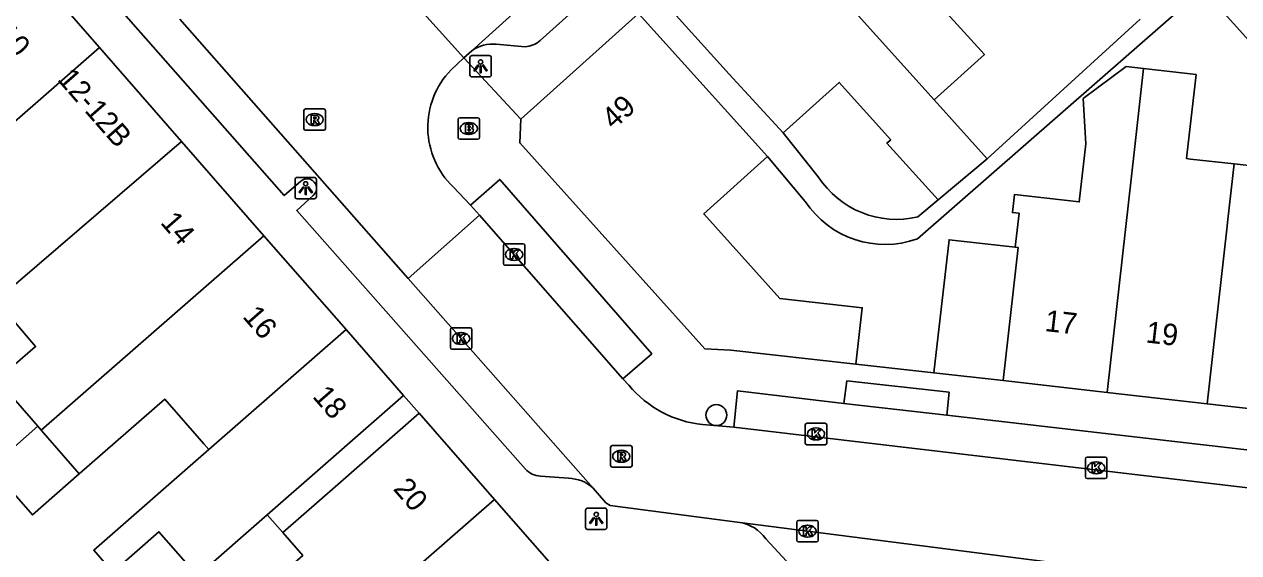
# Model space of a CAD drawing. Extents: x 162172 to 163187, y 382874 to 383684.
# Drawn here: x 162658.8 to 162715.5, y 383404.9 to 383429.6 of the extents above; entities that cross this region are included whole.
import ezdxf

# ---------------------------------------------------------------- set-up
doc = ezdxf.new("R2010")
doc.units = 0
for name, color, linetype in [('IMGEO_Boom', 7, 'Continuous'), ('IMGEO_Brandkraan', 7, 'Continuous'), ('IMGEO_Kolk', 7, 'Continuous'), ('IMGEO_Lichtpunt', 7, 'Continuous'), ('IMGEO_Pand', 7, 'Continuous'), ('IMGEO_Pand_nummerreeks', 7, 'Continuous'), ('IMGEO_Pand_overbouw', 7, 'Continuous'), ('IMGEO_Rijbaan_lokaal_open', 7, 'Continuous'), ('IMGEO_Rioolput', 7, 'Continuous'), ('IMGEO_Voetpad_open', 7, 'Continuous')]:
    doc.layers.add(name, color=color, linetype=linetype)

msp = doc.modelspace()

# ---------------------------------------------------------------- linework, layer by layer
at = {"layer": 'IMGEO_Boom'}
msp.add_circle((162691.134, 383411.373), 0.489, dxfattribs=at)
at = {"layer": 'IMGEO_Brandkraan'}
for p, q in [((162679.07, 383424.336), (162679.07, 383425.188)), ((162679.145, 383425.262), (162679.997, 383425.262)), ((162680.071, 383425.188), (162680.071, 383424.336)), ((162679.558, 383425.042), (162679.583, 383425.042)), ((162679.997, 383424.262), (162679.145, 383424.262)), ((162679.581, 383424.482), (162679.556, 383424.482))]:
    msp.add_line(p, q, dxfattribs=at)
for points in [[(162679.07, 383424.336), (162679.07, 383425.188)], [(162679.145, 383425.262), (162679.997, 383425.262)], [(162680.071, 383425.188), (162680.071, 383424.336)], [(162679.418, 383424.962), (162679.418, 383424.562), (162679.631, 383424.562)], [(162679.649, 383424.962), (162679.418, 383424.962)], [(162679.597, 383424.881), (162679.543, 383424.881), (162679.543, 383424.805)], [(162679.543, 383424.805), (162679.596, 383424.805)], [(162679.605, 383424.729), (162679.543, 383424.729), (162679.543, 383424.648)], [(162679.543, 383424.648), (162679.605, 383424.648)], [(162679.997, 383424.262), (162679.145, 383424.262)]]:
    msp.add_lwpolyline(points, dxfattribs=at)
for centre, radius, start, end in [((162679.147, 383425.186), 0.0765, 91.552, 178.448), ((162679.147, 383425.186), 0.0765, 91.552, 178.448), ((162679.995, 383425.186), 0.0765, 1.552, 88.448), ((162679.995, 383425.186), 0.0765, 1.552, 88.448), ((162679.598, 383424.843), 0.0379, 267.8285, 90.9355), ((162679.606, 383424.688), 0.0404, 269.8759, 90.5077), ((162679.637, 383424.813), 0.251, 268.6676, 293.5347), ((162679.653, 383424.817), 0.145, 59.4692, 91.5367), ((162679.678, 383424.864), 0.0922, 285.5137, 58.1501), ((162679.683, 383424.672), 0.105, 301.3115, 78.989), ((162679.147, 383424.338), 0.0765, 181.552, 268.448), ((162679.147, 383424.338), 0.0765, 181.552, 268.448), ((162679.995, 383424.338), 0.0765, 271.552, 358.448), ((162679.995, 383424.338), 0.0765, 271.552, 358.448)]:
    msp.add_arc(centre, radius, start, end, dxfattribs=at)
for centre, major_axis, ratio, start_param, end_param in [((162679.557, 383424.762), (-0.387, 0.002), 0.722429, 4.712389, 7.853982), ((162679.582, 383424.762), (-0.39, 0.002), 0.717154, 1.570796, 4.712389)]:
    msp.add_ellipse(centre, major_axis=major_axis, ratio=ratio, start_param=start_param, end_param=end_param, dxfattribs=at)
at = {"layer": 'IMGEO_Kolk'}
for p, q in [((162681.186, 383418.45), (162681.186, 383419.302)), ((162681.261, 383419.376), (162682.113, 383419.376)), ((162681.674, 383419.156), (162681.699, 383419.156)), ((162682.187, 383419.302), (162682.187, 383418.45)), ((162682.113, 383418.376), (162681.261, 383418.376)), ((162681.697, 383418.596), (162681.672, 383418.596)), ((162678.71, 383414.524), (162678.71, 383415.376)), ((162678.785, 383415.45), (162679.637, 383415.45)), ((162679.198, 383415.23), (162679.223, 383415.23)), ((162679.711, 383415.376), (162679.711, 383414.524)), ((162679.637, 383414.45), (162678.785, 383414.45)), ((162679.221, 383414.67), (162679.196, 383414.67)), ((162695.364, 383410.991), (162696.216, 383410.991)), ((162695.289, 383410.065), (162695.289, 383410.917)), ((162695.777, 383410.771), (162695.802, 383410.771)), ((162696.29, 383410.917), (162696.29, 383410.065)), ((162696.216, 383409.991), (162695.364, 383409.991)), ((162695.8, 383410.211), (162695.775, 383410.211)), ((162708.373, 383408.484), (162708.373, 383409.336)), ((162708.448, 383409.41), (162709.3, 383409.41)), ((162709.374, 383409.336), (162709.374, 383408.484)), ((162708.861, 383409.19), (162708.886, 383409.19)), ((162709.3, 383408.41), (162708.448, 383408.41)), ((162708.884, 383408.63), (162708.859, 383408.63)), ((162694.965, 383406.452), (162695.817, 383406.452)), ((162694.89, 383405.526), (162694.89, 383406.378)), ((162695.378, 383406.232), (162695.403, 383406.232)), ((162695.891, 383406.378), (162695.891, 383405.526)), ((162695.817, 383405.452), (162694.965, 383405.452)), ((162695.401, 383405.672), (162695.376, 383405.672))]:
    msp.add_line(p, q, dxfattribs=at)
for points in [[(162681.186, 383418.45), (162681.186, 383419.302)], [(162681.261, 383419.376), (162682.113, 383419.376)], [(162681.507, 383419.076), (162681.63, 383419.076), (162681.63, 383418.925), (162681.76, 383419.076), (162681.924, 383419.076), (162681.778, 383418.925), (162681.931, 383418.676), (162681.779, 383418.676), (162681.694, 383418.84), (162681.63, 383418.773), (162681.63, 383418.676), (162681.507, 383418.676), (162681.507, 383419.076)], [(162682.187, 383419.302), (162682.187, 383418.45)], [(162682.113, 383418.376), (162681.261, 383418.376)], [(162678.71, 383414.524), (162678.71, 383415.376)], [(162678.785, 383415.45), (162679.637, 383415.45)], [(162679.031, 383415.15), (162679.154, 383415.15), (162679.154, 383414.999), (162679.284, 383415.15), (162679.448, 383415.15), (162679.302, 383414.999), (162679.455, 383414.75), (162679.303, 383414.75), (162679.218, 383414.914), (162679.154, 383414.847), (162679.154, 383414.75), (162679.031, 383414.75), (162679.031, 383415.15)], [(162679.711, 383415.376), (162679.711, 383414.524)], [(162679.637, 383414.45), (162678.785, 383414.45)], [(162695.364, 383410.991), (162696.216, 383410.991)], [(162695.289, 383410.065), (162695.289, 383410.917)], [(162695.61, 383410.691), (162695.733, 383410.691), (162695.733, 383410.54), (162695.863, 383410.691), (162696.027, 383410.691), (162695.881, 383410.54), (162696.034, 383410.291), (162695.882, 383410.291), (162695.797, 383410.455), (162695.733, 383410.388), (162695.733, 383410.291), (162695.61, 383410.291), (162695.61, 383410.691)], [(162696.29, 383410.917), (162696.29, 383410.065)], [(162696.216, 383409.991), (162695.364, 383409.991)], [(162708.373, 383408.484), (162708.373, 383409.336)], [(162708.448, 383409.41), (162709.3, 383409.41)], [(162709.374, 383409.336), (162709.374, 383408.484)], [(162708.694, 383409.11), (162708.817, 383409.11), (162708.817, 383408.959), (162708.947, 383409.11), (162709.111, 383409.11), (162708.965, 383408.959), (162709.118, 383408.71), (162708.966, 383408.71), (162708.881, 383408.874), (162708.817, 383408.807), (162708.817, 383408.71), (162708.694, 383408.71), (162708.694, 383409.11)], [(162709.3, 383408.41), (162708.448, 383408.41)], [(162694.965, 383406.452), (162695.817, 383406.452)], [(162694.89, 383405.526), (162694.89, 383406.378)], [(162695.211, 383406.152), (162695.334, 383406.152), (162695.334, 383406.001), (162695.464, 383406.152), (162695.628, 383406.152), (162695.482, 383406.001), (162695.635, 383405.752), (162695.483, 383405.752), (162695.398, 383405.916), (162695.334, 383405.849), (162695.334, 383405.752), (162695.211, 383405.752), (162695.211, 383406.152)], [(162695.891, 383406.378), (162695.891, 383405.526)], [(162695.817, 383405.452), (162694.965, 383405.452)]]:
    msp.add_lwpolyline(points, dxfattribs=at)
for centre, start, end in [((162681.263, 383419.3), 91.552, 178.448), ((162681.263, 383419.3), 91.552, 178.448), ((162682.111, 383419.3), 1.552, 88.448), ((162682.111, 383419.3), 1.552, 88.448), ((162681.263, 383418.452), 181.552, 268.448), ((162681.263, 383418.452), 181.552, 268.448), ((162682.111, 383418.452), 271.552, 358.448), ((162682.111, 383418.452), 271.552, 358.448), ((162678.787, 383415.374), 91.552, 178.448), ((162678.787, 383415.374), 91.552, 178.448), ((162679.635, 383415.374), 1.552, 88.448), ((162679.635, 383415.374), 1.552, 88.448), ((162678.787, 383414.526), 181.552, 268.448), ((162678.787, 383414.526), 181.552, 268.448), ((162679.635, 383414.526), 271.552, 358.448), ((162679.635, 383414.526), 271.552, 358.448), ((162695.366, 383410.915), 91.552, 178.448), ((162695.366, 383410.915), 91.552, 178.448), ((162696.214, 383410.915), 1.552, 88.448), ((162696.214, 383410.915), 1.552, 88.448), ((162695.366, 383410.067), 181.552, 268.448), ((162695.366, 383410.067), 181.552, 268.448), ((162696.214, 383410.067), 271.552, 358.448), ((162696.214, 383410.067), 271.552, 358.448), ((162708.45, 383409.334), 91.552, 178.448), ((162708.45, 383409.334), 91.552, 178.448), ((162709.298, 383409.334), 1.552, 88.448), ((162709.298, 383409.334), 1.552, 88.448), ((162708.45, 383408.486), 181.552, 268.448), ((162708.45, 383408.486), 181.552, 268.448), ((162709.298, 383408.486), 271.552, 358.448), ((162709.298, 383408.486), 271.552, 358.448), ((162694.967, 383406.376), 91.552, 178.448), ((162694.967, 383406.376), 91.552, 178.448), ((162695.815, 383406.376), 1.552, 88.448), ((162695.815, 383406.376), 1.552, 88.448), ((162694.967, 383405.528), 181.552, 268.448), ((162694.967, 383405.528), 181.552, 268.448), ((162695.815, 383405.528), 271.552, 358.448), ((162695.815, 383405.528), 271.552, 358.448)]:
    msp.add_arc(centre, 0.0765, start, end, dxfattribs=at)
for centre, major_axis, ratio, start_param, end_param in [((162681.673, 383418.876), (-0.387, 0.002), 0.722429, 4.712389, 7.853982), ((162681.698, 383418.876), (-0.39, 0.002), 0.717154, 1.570796, 4.712389), ((162679.197, 383414.95), (-0.387, 0.002), 0.722429, 4.712389, 7.853982), ((162679.222, 383414.95), (-0.39, 0.002), 0.717154, 1.570796, 4.712389), ((162695.776, 383410.491), (-0.387, 0.002), 0.722429, 4.712389, 7.853982), ((162695.801, 383410.491), (-0.39, 0.002), 0.717154, 1.570796, 4.712389), ((162708.86, 383408.91), (-0.387, 0.002), 0.722429, 4.712389, 7.853982), ((162708.885, 383408.91), (-0.39, 0.002), 0.717154, 1.570796, 4.712389), ((162695.377, 383405.952), (-0.387, 0.002), 0.722429, 4.712389, 7.853982), ((162695.402, 383405.952), (-0.39, 0.002), 0.717154, 1.570796, 4.712389)]:
    msp.add_ellipse(centre, major_axis=major_axis, ratio=ratio, start_param=start_param, end_param=end_param, dxfattribs=at)
at = {"layer": 'IMGEO_Lichtpunt'}
for p, q in [((162679.624, 383428.071), (162679.624, 383427.264)), ((162679.624, 383428.071), (162679.624, 383427.264)), ((162680.526, 383428.166), (162679.718, 383428.166)), ((162680.526, 383428.166), (162679.718, 383428.166)), ((162680.62, 383427.264), (162680.62, 383428.071)), ((162680.62, 383427.264), (162680.62, 383428.071)), ((162679.718, 383427.17), (162680.526, 383427.17)), ((162679.718, 383427.17), (162680.526, 383427.17)), ((162671.454, 383422.378), (162671.454, 383421.571)), ((162671.454, 383422.378), (162671.454, 383421.571)), ((162672.356, 383422.473), (162671.548, 383422.473)), ((162672.356, 383422.473), (162671.548, 383422.473)), ((162672.45, 383421.571), (162672.45, 383422.378)), ((162672.45, 383421.571), (162672.45, 383422.378)), ((162671.548, 383421.477), (162672.356, 383421.477)), ((162671.548, 383421.477), (162672.356, 383421.477)), ((162685.928, 383407.028), (162685.12, 383407.028)), ((162685.928, 383407.028), (162685.12, 383407.028)), ((162685.026, 383406.933), (162685.026, 383406.126)), ((162685.026, 383406.933), (162685.026, 383406.126)), ((162686.022, 383406.126), (162686.022, 383406.933)), ((162686.022, 383406.126), (162686.022, 383406.933)), ((162685.12, 383406.032), (162685.928, 383406.032)), ((162685.12, 383406.032), (162685.928, 383406.032))]:
    msp.add_line(p, q, dxfattribs=at)
for points in [[(162679.998, 383427.735), (162680.037, 383427.707), (162679.849, 383427.445), (162679.811, 383427.472), (162679.998, 383427.735)], [(162680.1, 383427.687), (162680.147, 383427.687), (162680.147, 383427.365), (162680.1, 383427.365), (162680.1, 383427.687)], [(162680.21, 383427.707), (162680.248, 383427.734), (162680.435, 383427.472), (162680.396, 383427.444), (162680.21, 383427.707)], [(162671.828, 383422.042), (162671.867, 383422.014), (162671.679, 383421.752), (162671.641, 383421.779), (162671.828, 383422.042)], [(162671.93, 383421.994), (162671.977, 383421.994), (162671.977, 383421.672), (162671.93, 383421.672), (162671.93, 383421.994)], [(162672.04, 383422.014), (162672.078, 383422.041), (162672.265, 383421.779), (162672.226, 383421.751), (162672.04, 383422.014)], [(162685.4, 383406.597), (162685.439, 383406.569), (162685.251, 383406.307), (162685.213, 383406.334), (162685.4, 383406.597)], [(162685.502, 383406.549), (162685.549, 383406.549), (162685.549, 383406.227), (162685.502, 383406.227), (162685.502, 383406.549)], [(162685.612, 383406.569), (162685.65, 383406.596), (162685.837, 383406.334), (162685.798, 383406.306), (162685.612, 383406.569)]]:
    msp.add_lwpolyline(points, dxfattribs=at)
for centre in [(162680.123, 383427.869), (162671.953, 383422.176), (162685.525, 383406.731)]:
    msp.add_circle(centre, 0.0994, dxfattribs=at)
for centre, start, end in [((162679.718, 383428.071), 90, 180), ((162679.718, 383428.071), 90, 180), ((162680.526, 383428.071), 0, 90), ((162680.526, 383428.071), 0, 90), ((162679.718, 383427.264), 180, 270), ((162679.718, 383427.264), 180, 270), ((162680.526, 383427.264), 270, 0), ((162680.526, 383427.264), 270, 360), ((162671.548, 383422.378), 90, 180), ((162671.548, 383422.378), 90, 180), ((162672.356, 383422.378), 0, 90), ((162672.356, 383422.378), 0, 90), ((162671.548, 383421.571), 180, 270), ((162671.548, 383421.571), 180, 270), ((162672.356, 383421.571), 270, 0), ((162672.356, 383421.571), 270, 360), ((162685.12, 383406.933), 90, 180), ((162685.12, 383406.933), 90, 180), ((162685.928, 383406.933), 0, 90), ((162685.928, 383406.933), 0, 90), ((162685.12, 383406.126), 180, 270), ((162685.12, 383406.126), 180, 270), ((162685.928, 383406.126), 270, 0), ((162685.928, 383406.126), 270, 360)]:
    msp.add_arc(centre, 0.0946, start, end, dxfattribs=at)
at = {"layer": 'IMGEO_Pand'}
for points in [[(162701.304, 383426.1), (162693.085, 383435.246)], [(162701.304, 383426.1), (162703.652, 383428.211), (162701.261, 383430.871), (162703.723, 383433.084)], [(162658.471, 383432.944), (162662.315, 383428.547)], [(162694.249, 383424.557), (162691.729, 383427.304), (162688.386, 383431.022)], [(162687.503, 383430.138), (162682.005, 383425.195)], [(162687.503, 383430.138), (162693.52, 383423.445)], [(162662.315, 383428.547), (162655.851, 383422.895)], [(162666.159, 383424.151), (162662.315, 383428.547)], [(162705.098, 383419.217), (162705.277, 383420.801), (162704.964, 383420.836), (162705.058, 383421.671), (162708.086, 383421.328), (162708.393, 383424.04), (162708.273, 383426.159), (162710.274, 383427.651), (162711.093, 383427.559)], [(162709.382, 383412.436), (162710.666, 383423.783), (162711.093, 383427.559)], [(162711.093, 383427.559), (162713.543, 383427.282), (162713.117, 383423.505), (162713.1, 383423.356), (162713.279, 383423.335), (162715.325, 383423.104)], [(162694.249, 383424.557), (162696.875, 383426.916), (162699.282, 383424.238), (162699.103, 383424.077), (162701.49, 383421.421)], [(162703.785, 383423.338), (162701.304, 383426.1)], [(162697.654, 383413.757), (162691.813, 383414.407), (162690.592, 383414.472), (162681.947, 383424.088), (162682.005, 383425.195)], [(162715.325, 383423.104), (162717.531, 383422.854), (162717.804, 383425.263), (162717.817, 383425.378), (162720.286, 383425.098), (162720.273, 383424.984)], [(162657.489, 383416.733), (162666.159, 383424.151)], [(162666.159, 383424.151), (162670.003, 383419.754)], [(162693.52, 383423.445), (162690.546, 383420.771), (162694.105, 383416.814), (162697.946, 383416.386), (162697.654, 383413.757)], [(162703.785, 383423.338), (162701.49, 383421.421)], [(162715.325, 383423.104), (162715.031, 383420.508), (162714.981, 383420.063), (162714.057, 383411.906)], [(162659.603, 383410.662), (162670.003, 383419.754)], [(162670.003, 383419.754), (162673.839, 383415.368)], [(162701.297, 383413.351), (162702.002, 383419.567), (162705.098, 383419.217)], [(162705.098, 383419.217), (162705.236, 383419.2), (162704.532, 383412.985)], [(162657.489, 383416.733), (162659.334, 383414.576), (162657.524, 383413.027), (162657.649, 383412.894), (162659.439, 383410.849)], [(162673.839, 383415.368), (162667.431, 383409.765)], [(162673.839, 383415.368), (162676.527, 383412.293)], [(162704.532, 383412.985), (162701.297, 383413.351)], [(162709.382, 383412.436), (162704.532, 383412.985)], [(162661.379, 383408.632), (162665.368, 383412.123), (162667.196, 383410.034), (162667.431, 383409.765)], [(162667.431, 383409.765), (162662.05, 383405.061), (162662.943, 383404.041), (162665.093, 383405.923), (162666.894, 383403.864), (162670.157, 383406.719), (162672.756, 383408.993), (162676.527, 383412.293)], [(162714.057, 383411.906), (162709.382, 383412.436)], [(162718.732, 383411.377), (162714.057, 383411.906)], [(162677.251, 383411.459), (162673.45, 383408.133), (162670.884, 383405.888), (162671.817, 383404.822), (162667.629, 383401.158), (162670.103, 383398.331), (162670.213, 383398.206)], [(162677.251, 383411.459), (162680.771, 383407.436)], [(162659.439, 383410.849), (162657.247, 383408.93), (162659.187, 383406.714), (162661.379, 383408.632)], [(162659.603, 383410.662), (162659.439, 383410.849)], [(162661.379, 383408.632), (162659.603, 383410.662)], [(162670.213, 383398.206), (162680.771, 383407.436)], [(162680.771, 383407.436), (162684.317, 383403.384), (162687.08, 383403.199)]]:
    msp.add_lwpolyline(points, dxfattribs=at)
at = {"layer": 'IMGEO_Pand_overbouw'}
msp.add_lwpolyline([(162677.251, 383411.459), (162676.527, 383412.293), (162672.756, 383408.993), (162670.157, 383406.719), (162670.884, 383405.888), (162673.45, 383408.133)], close=True, dxfattribs=at)
at = {"layer": 'IMGEO_Rijbaan_lokaal_open'}
for points in [[(162715.496, 383460.436), (162713.601, 383458.84), (162697.961, 383444.869), (162679.717, 383428.393)], [(162679.332, 383428.059), (162676.183, 383431.58)], [(162676.74, 383417.761), (162666.079, 383429.865)], [(162679.332, 383428.059), (162678.73, 383427.487)], [(162679.332, 383428.059), (162679.717, 383428.393)], [(162678.841, 383422.038), (162679.645, 383421.175)], [(162680.069, 383420.719), (162679.645, 383421.175)], [(162680.069, 383420.719), (162676.74, 383417.761)], [(162686.77, 383413.066), (162680.069, 383420.719)], [(162676.74, 383417.761), (162685.378, 383407.959)], [(162687.048, 383412.766), (162686.77, 383413.066)], [(162691.943, 383410.803), (162690.489, 383410.931)], [(162727.575, 383406.608), (162691.943, 383410.803)], [(162692.226, 383406.357), (162692.108, 383406.372), (162686.175, 383407.146), (162685.977, 383407.278), (162685.378, 383407.959)], [(162692.226, 383406.357), (162721.544, 383402.607), (162725.462, 383402.102)]]:
    msp.add_lwpolyline(points, dxfattribs=at)
for centre, radius, start, end in [((162681.503, 383424.818), 3.849, 136.0958, 226.2382), ((162691.01, 383416.052), 5.147, 219.6695, 264.1907)]:
    msp.add_arc(centre, radius, start, end, dxfattribs=at)
at = {"layer": 'IMGEO_Rioolput'}
for p, q in [((162671.87, 383424.751), (162671.87, 383425.603)), ((162671.945, 383425.677), (162672.797, 383425.677)), ((162672.358, 383425.457), (162672.383, 383425.457)), ((162672.871, 383425.603), (162672.871, 383424.751)), ((162672.797, 383424.677), (162671.945, 383424.677)), ((162672.381, 383424.897), (162672.356, 383424.897)), ((162686.193, 383409.022), (162686.193, 383409.874)), ((162686.268, 383409.948), (162687.12, 383409.948)), ((162687.194, 383409.874), (162687.194, 383409.022)), ((162686.681, 383409.728), (162686.706, 383409.728)), ((162687.12, 383408.948), (162686.268, 383408.948)), ((162686.704, 383409.168), (162686.679, 383409.168))]:
    msp.add_line(p, q, dxfattribs=at)
for points in [[(162671.87, 383424.751), (162671.87, 383425.603)], [(162671.945, 383425.677), (162672.797, 383425.677)], [(162672.459, 383425.375), (162672.207, 383425.377), (162672.207, 383424.977)], [(162672.207, 383424.977), (162672.331, 383424.977), (162672.331, 383425.139), (162672.342, 383425.139)], [(162672.385, 383425.296), (162672.331, 383425.296), (162672.331, 383425.215)], [(162672.331, 383425.215), (162672.383, 383425.215)], [(162672.871, 383425.603), (162672.871, 383424.751)], [(162672.797, 383424.677), (162671.945, 383424.677)], [(162672.389, 383425.11), (162672.46, 383424.977), (162672.6, 383424.977), (162672.535, 383425.103)], [(162686.193, 383409.022), (162686.193, 383409.874)], [(162686.268, 383409.948), (162687.12, 383409.948)], [(162687.194, 383409.874), (162687.194, 383409.022)], [(162686.782, 383409.646), (162686.53, 383409.648), (162686.53, 383409.248)], [(162686.53, 383409.248), (162686.654, 383409.248), (162686.654, 383409.41), (162686.665, 383409.41)], [(162686.708, 383409.567), (162686.654, 383409.567), (162686.654, 383409.486)], [(162686.654, 383409.486), (162686.706, 383409.486)], [(162686.712, 383409.381), (162686.783, 383409.248), (162686.923, 383409.248), (162686.858, 383409.374)], [(162687.12, 383408.948), (162686.268, 383408.948)]]:
    msp.add_lwpolyline(points, dxfattribs=at)
for centre, radius, start, end in [((162671.947, 383425.601), 0.0765, 91.552, 178.448), ((162671.947, 383425.601), 0.0765, 91.552, 178.448), ((162672.341, 383425.086), 0.0533, 26.0293, 88.6989), ((162672.367, 383425.404), 0.19, 274.7715, 282.9687), ((162672.391, 383425.2), 0.0964, 77.0061, 93.1865), ((162672.405, 383425.257), 0.0378, 276.6634, 79.6772), ((162672.458, 383425.265), 0.109, 350.3612, 89.416), ((162672.456, 383425.265), 0.112, 277.5842, 350.9817), ((162672.44, 383425.05), 0.108, 29.5134, 73.7905), ((162672.795, 383425.601), 0.0765, 1.552, 88.448), ((162672.795, 383425.601), 0.0765, 1.552, 88.448), ((162671.947, 383424.753), 0.0765, 181.552, 268.448), ((162671.947, 383424.753), 0.0765, 181.552, 268.448), ((162672.795, 383424.753), 0.0765, 271.552, 358.448), ((162672.795, 383424.753), 0.0765, 271.552, 358.448), ((162686.27, 383409.872), 0.0765, 91.552, 178.448), ((162686.27, 383409.872), 0.0765, 91.552, 178.448), ((162687.118, 383409.872), 0.0765, 1.552, 88.448), ((162687.118, 383409.872), 0.0765, 1.552, 88.448), ((162686.664, 383409.357), 0.0533, 26.0293, 88.6989), ((162686.69, 383409.675), 0.19, 274.7715, 282.9687), ((162686.714, 383409.471), 0.0964, 77.0061, 93.1865), ((162686.728, 383409.528), 0.0378, 276.6634, 79.6772), ((162686.781, 383409.536), 0.109, 350.3612, 89.416), ((162686.779, 383409.536), 0.112, 277.5842, 350.9817), ((162686.763, 383409.321), 0.108, 29.5134, 73.7905), ((162686.27, 383409.024), 0.0765, 181.552, 268.448), ((162686.27, 383409.024), 0.0765, 181.552, 268.448), ((162687.118, 383409.024), 0.0765, 271.552, 358.448), ((162687.118, 383409.024), 0.0765, 271.552, 358.448)]:
    msp.add_arc(centre, radius, start, end, dxfattribs=at)
for centre, major_axis, ratio, start_param, end_param in [((162672.357, 383425.177), (-0.387, 0.002), 0.722429, 4.712389, 7.853982), ((162672.382, 383425.177), (-0.39, 0.002), 0.717154, 1.570796, 4.712389), ((162686.68, 383409.448), (-0.387, 0.002), 0.722429, 4.712389, 7.853982), ((162686.705, 383409.448), (-0.39, 0.002), 0.717154, 1.570796, 4.712389)]:
    msp.add_ellipse(centre, major_axis=major_axis, ratio=ratio, start_param=start_param, end_param=end_param, dxfattribs=at)
at = {"layer": 'IMGEO_Voetpad_open'}
for points in [[(162671.728, 383422.304), (162670.947, 383421.624), (162656.152, 383438.415), (162652.44, 383442.612), (162638.339, 383458.626), (162634.87, 383462.537), (162626.982, 383471.52)], [(162682.9, 383428.866), (162695.892, 383440.51), (162695.2, 383441.281)], [(162700.525, 383419.608), (162713.853, 383431.266), (162716.715, 383428.083), (162717.873, 383427.924), (162719.751, 383429.576), (162729.561, 383438.208)], [(162710.931, 383429.869), (162703.785, 383423.338)], [(162680.846, 383428.7), (162682.201, 383428.579)], [(162682.005, 383425.195), (162679.332, 383428.059)], [(162695.895, 383422.509), (162694.249, 383424.557)], [(162693.52, 383423.445), (162695.287, 383421.354)], [(162679.645, 383421.175), (162681.018, 383422.382), (162688.114, 383414.239), (162686.77, 383413.066)], [(162682.214, 383408.852), (162671.533, 383420.932), (162672.304, 383421.631)], [(162701.49, 383421.421), (162700.549, 383420.635)], [(162697.654, 383413.757), (162701.297, 383413.351)], [(162697.087, 383411.919), (162697.227, 383412.97), (162702.005, 383412.443), (162701.898, 383411.367)], [(162676.527, 383412.293), (162677.251, 383411.459)], [(162691.943, 383410.803), (162692.119, 383412.501), (162697.087, 383411.919)], [(162701.898, 383411.367), (162697.087, 383411.919)], [(162701.898, 383411.367), (162727.754, 383408.381), (162727.575, 383406.608)], [(162684.226, 383408.42), (162682.923, 383408.525)], [(162694.409, 383404.551), (162693.439, 383405.594)]]:
    msp.add_lwpolyline(points, dxfattribs=at)
for centre, radius, start, end in [((162680.691, 383427.042), 1.665, 84.6478, 125.7766), ((162682.109, 383429.797), 1.222, 274.3084, 310.3363), ((162672.019, 383421.97), 0.443, 310.0076, 131.1108), ((162699.542, 383424.85), 4.334, 212.6978, 283.4364), ((162699.009, 383423.789), 4.447, 213.1956, 289.9345), ((162682.947, 383409.508), 0.984, 221.8604, 268.62), ((162684.211, 383406.713), 1.707, 46.8824, 89.4977), ((162691.943, 383404.562), 1.818, 34.6134, 81.0452)]:
    msp.add_arc(centre, radius, start, end, dxfattribs=at)

# ---------------------------------------------------------------- texts
at = {"layer": 'IMGEO_Pand_nummerreeks'}
for s, rotation, p in [('10', 311.1611, (162657.442, 383429.138)), ('12-12B', 311.1668, (162660.315, 383427.038)), ('49', 41.9573, (162686.333, 383424.675)), ('14', 311.1611, (162665.128, 383420.347)), ('16', 311.1725, (162668.968, 383415.955)), ('17', 353.5428, (162706.445, 383415.302)), ('19', 353.5428, (162711.164, 383414.768)), ('18', 311.1553, (162672.232, 383412.223)), ('20', 311.2, (162676.001, 383407.907))]:
    msp.add_text(s, height=1, rotation=rotation, dxfattribs=at).set_placement(p)

doc.saveas('drawing.dxf')
